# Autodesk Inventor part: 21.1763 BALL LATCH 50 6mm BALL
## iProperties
Created: 2007-03
Part Number: 21.1763 BALL LATCH 50 6mm BALL
Document SubType Name: Modeling
Designer: Andy Moles
Material: Steel
Mass: 0.887814 g
Surface Area: 1.13097 cm^2
Volume: 0.113097 cm^3
Density: 7.85 g/cm^3
Author: Andy Moles
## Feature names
1. Revolution1
